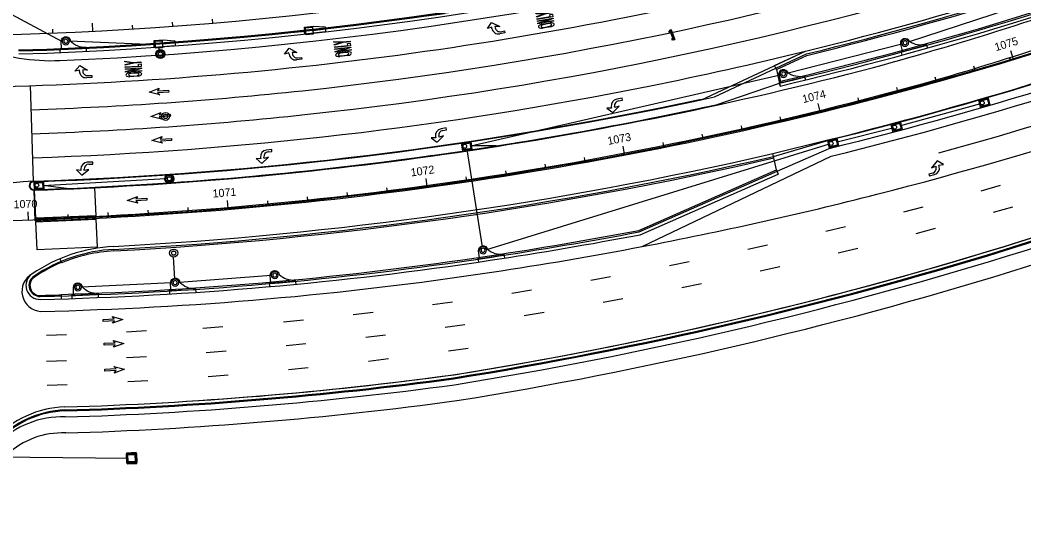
# Model space of a CAD drawing. Extents: x 468143 to 491361, y 1438528 to 1468730.
# Drawn here: x 489201 to 489702, y 1466536 to 1466783 of the extents above; entities that cross this region are included whole.
import ezdxf

# ---------------------------------------------------------------- set-up
doc = ezdxf.new("R2010")
doc.units = 0
doc.layers.add('Default', color=7, linetype='Continuous')
doc.layers.add('Xreference_dp', color=7, linetype='Continuous')

# ---------------------------------------------------------------- blocks, each defined once
blk = doc.blocks.new('POINT_DISPLAY')
at = {"layer": 'Default'}
blk.add_line((0, 0), (0, 0), dxfattribs=at)
blk = doc.blocks.new('InltCurb1_35')
at = {"layer": 'Default'}
for p, q in [((2.25, 2), (2.25, 5.5)), ((-10, 2), (-10, 0)), ((-10, 1.5), (3, 1.5)), ((3, 2), (2.25, 2)), ((3, 0), (3, 2))]:
    blk.add_line(p, q, dxfattribs=at)
for radius in [1.75, 1]:
    blk.add_circle((0, 5.5), radius, dxfattribs=at)
for centre, radius, start, end in [((-9.85, 12), 10, 269.1432, 319.4677), ((0, 5.5), 2.25, 0, 180)]:
    blk.add_arc(centre, radius, start, end, dxfattribs=at)
for p in [(-1.75, 5.5), (-1.75, 5.5), (-1.6, 6.2), (-1.22, 6.76), (-0.66, 7.12), (0, 7.75), (0, 7.25), (0, 7.25), (0, 5.5), (0, 5.5), (0.7, 7.1), (1.26, 6.72), (1.62, 6.16), (1.75, 5.5), (1.75, 5.5), (-1.62, 4.84), (-1.26, 4.28), (-0.7, 3.9), (0, 3.75), (0, 3.75), (0, 0), (0, 0), (0.66, 3.88), (1.22, 4.24), (1.6, 4.8)]:
    blk.add_blockref('POINT_DISPLAY', p, dxfattribs=at)
blk = doc.blocks.new('InltCurb7_40')
at = {"layer": 'Default'}
for p, q in [((2.5, 4), (-2.5, 4)), ((-2.5, 4), (-2.5, 0)), ((2.5, 3.25), (-2.5, 3.25)), ((-2.5, 0.75), (2.5, 0.75)), ((-2.5, 0), (2.5, 0)), ((2.5, 0), (2.5, 4))]:
    blk.add_line(p, q, dxfattribs=at)
blk.add_lwpolyline([(-2, 0.5), (2, 0.5), (2, 3.5), (-2, 3.5)], close=True, dxfattribs=at)
blk.add_circle((-1.04, 2.19), 1, dxfattribs=at)
for p in [(-2, 3.5), (-2, 2), (-2, 2), (-2, 0.5), (0, 4), (0, 3.5), (0, 3.5), (0, 2), (0, 2), (0, 0.5), (0, 0.5), (0, 0), (0, 0), (2, 3.5), (2, 2), (2, 2), (2, 0.5)]:
    blk.add_blockref('POINT_DISPLAY', p, dxfattribs=at)
blk = doc.blocks.new('MHCover2')
at = {"layer": 'Default'}
for radius in [2, 1.06, 1]:
    blk.add_circle((0, 0), radius, dxfattribs=at)
for p in [(-2, 0), (-2, 0), (-1.83, 0.81), (-1.39, 1.43), (-0.75, 1.85), (0, 2.5), (0, 2), (0, 2), (0, 0), (0, 0), (0, 0), (0.81, 1.83), (1.43, 1.39), (1.85, 0.75), (2, 0), (2, 0), (-1.85, -0.75), (-1.43, -1.39), (-0.81, -1.83), (0, -2), (0, -2), (0, -2.5), (0.75, -1.85), (1.39, -1.43), (1.83, -0.81)]:
    blk.add_blockref('POINT_DISPLAY', p, dxfattribs=at)
blk = doc.blocks.new('PBottom35Dia')
at = {"layer": 'Default'}
for radius in [2.25, 1.75, 1.75]:
    blk.add_circle((0, 0), radius, dxfattribs=at)
for p in [(-1.75, 0), (-1.75, 0), (-1.6, 0.7), (-1.22, 1.26), (-0.66, 1.62), (0, 1.75), (0, 1.75), (0, 1.75), (0, 0), (0, 0), (0.7, 1.6), (1.26, 1.22), (1.62, 0.66), (1.75, 0), (1.75, 0), (-1.62, -0.66), (-1.26, -1.22), (-0.7, -1.6), (0, -1.75), (0, -1.75), (0, -1.75), (0.66, -1.62), (1.22, -1.26), (1.6, -0.7)]:
    blk.add_blockref('POINT_DISPLAY', p, dxfattribs=at)
blk = doc.blocks.new('DBIDnoPvt')
at = {"layer": 'Default'}
for p, q in [((2.21, 2.71), (-2.21, 2.71)), ((-2.21, 2.71), (-2.21, -2.71)), ((-1.54, 2.23), (-1.54, -2.23)), ((1.54, 2.23), (-1.54, 2.23)), ((1.54, 2.04), (-1.54, 2.04)), ((1.54, -2.23), (1.54, 2.23)), ((2.21, -2.71), (2.21, 2.71)), ((-2.21, -2.71), (2.21, -2.71)), ((-1.54, -2.04), (1.54, -2.04)), ((-1.54, -2.23), (1.54, -2.23))]:
    blk.add_line(p, q, dxfattribs=at)
for p in [(-1.54, 2.04), (-1.54, 0), (-1.54, 0), (0, 2.71), (0, 2.04), (0, 2.04), (1.54, 2.04), (-1.54, -2.04), (0, 0), (0, 0), (0, -2.04), (0, -2.04), (0, -2.71), (1.54, 0), (1.54, 0), (1.54, -2.04)]:
    blk.add_blockref('POINT_DISPLAY', p, dxfattribs=at)
blk = doc.blocks.new('JBottom35x40')
at = {"layer": 'Default'}
for p, q in [((-2.42, 2.67), (-2.42, -2.67)), ((2.42, 2.67), (-2.42, 2.67)), ((-1.75, -2), (-1.75, 2)), ((-1.75, 2), (1.75, 2)), ((1.75, 2), (1.75, -2)), ((2.42, -2.67), (2.42, 2.67)), ((-2.42, -2.67), (2.42, -2.67)), ((1.75, -2), (-1.75, -2))]:
    blk.add_line(p, q, dxfattribs=at)
for p in [(-1.75, 2), (-1.75, 0), (-1.75, 0), (0, 2), (0, 2), (0, 2), (0, 0), (0, 0), (0, 0), (1.75, 2), (1.75, 0), (1.75, 0), (-1.75, -2), (0, -2), (0, -2), (0, -2), (1.75, -2)]:
    blk.add_blockref('POINT_DISPLAY', p, dxfattribs=at)
blk = doc.blocks.new('InltCurb5')
at = {"layer": 'Default'}
for p, q in [((-2.25, 3.5), (-8, 2.5)), ((-8, 2.5), (-8, 0)), ((-8, 1.5), (2.5, 1.5)), ((-8, 0), (2.5, 0)), ((2.25, 3.5), (-2.25, 3.5)), ((-1.96, 0), (-1.96, 1.5)), ((1.95, 0), (1.95, 1.5)), ((2.25, 2), (2.25, 3.5)), ((2.5, 2), (2.25, 2)), ((2.5, 0), (2.5, 2))]:
    blk.add_line(p, q, dxfattribs=at)
blk.add_lwpolyline([(-1.75, -0.5), (1.75, -0.5), (1.75, 3), (-1.75, 3)], close=True, dxfattribs=at)
for p in [(-1.75, 3), (-1.75, 1.25), (-1.75, 1.25), (0, 3.5), (0, 3), (0, 3), (0, 1.25), (0, 1.25), (1.75, 3), (1.75, 1.25), (1.75, 1.25), (-1.75, -0.5), (0, 0), (0, 0), (0, -0.5), (0, -0.5), (1.75, -0.5)]:
    blk.add_blockref('POINT_DISPLAY', p, dxfattribs=at)
blk = doc.blocks.new('SN')
at = {"layer": 'Default'}
for p, q in [((-0.064, 0.008), (-0.064, -0.008)), ((0.064, 0.008), (-0.064, 0.008)), ((0.064, -0.008), (0.064, 0.008)), ((-0.064, -0.008), (0.064, -0.008))]:
    blk.add_line(p, q, dxfattribs=at)
blk.add_lwpolyline([(-0.064, 0.008), (0.064, 0.008), (0.064, -0.008), (-0.064, -0.008)], close=True, dxfattribs=at)
for centre, start, end in [((-0.051, 0.02), 0, 180), ((-0.051, 0.02), 180, 0), ((0.05, 0.02), 0, 180), ((0.05, 0.02), 180, 0)]:
    blk.add_arc(centre, 0.00691, start, end, dxfattribs=at)
blk = doc.blocks.new('DAThru_1')
at = {"layer": 'Default'}
blk.add_lwpolyline([(4.58, -1.67), (5.58, -0.5), (0, -0.5), (0, 0.5), (5.58, 0.5), (4.58, 1.67), (9.83, 0), (4.58, -1.67)], dxfattribs=at)
blk = doc.blocks.new('DARightTurn')
at = {"layer": 'Default'}
for points in [[(2, 2.17), (0, 2.17), (0, 3.17), (2.67, 3.17)], [(5.67, -3.17), (2, -0.5), (4.33, -0.83), (4.33, -0.17)], [(6, -0.17), (6, -0.83), (8.25, -0.5), (5.67, -3.17)]]:
    blk.add_lwpolyline(points, dxfattribs=at)
for centre, radius in [((2, -0.17), 2.33), ((2.67, -0.17), 3.33)]:
    blk.add_arc(centre, radius, 360, 90, dxfattribs=at)
blk = doc.blocks.new('ONLY_5')
at = {"layer": 'Default'}
for p, q in [((1.94, 3.96), (6.06, 3.96)), ((6.06, 1.96), (1.94, 1.96)), ((5.6, 3.63), (2.4, 3.63)), ((2.4, 2.29), (5.6, 2.29))]:
    blk.add_line(p, q, dxfattribs=at)
for points in [[(0, -0.12), (0, 0.21), (5, 1.13), (0, 1.13), (0, 1.46), (8, 1.46), (8, 1.13), (2.9, 0.21), (8, 0.21), (8, -0.12), (0, -0.12)], [(1.33, -2.12), (0, -2.12), (0, -0.79), (8, -0.79), (8, -1.12), (1.33, -1.12), (1.33, -2.12)], [(8, -3.96), (3.67, -3.12), (0, -3.12), (0, -2.79), (3.67, -2.79), (8, -1.96), (8, -2.3), (4.57, -2.96), (8, -3.62), (8, -3.96)]]:
    blk.add_lwpolyline(points, dxfattribs=at)
for major_axis, ratio, start_param, end_param in [((4, 0), 0.291667, 2.111896, 4.171289), ((2.67, 0), 0.3125, 2.214297, 4.068888), ((2.67, 0), 0.3125, 5.35589, 7.210481), ((4, 0), 0.291667, 5.253489, 7.312882)]:
    blk.add_ellipse((4, 2.96), major_axis=major_axis, ratio=ratio, start_param=start_param, end_param=end_param, dxfattribs=at)
blk = doc.blocks.new('DALeftTurn_1')
at = {"layer": 'Default'}
for points in [[(5.67, 3.17), (2, 0.5), (4.33, 0.83), (4.33, 0.17)], [(6, 0.17), (6, 0.83), (8.25, 0.5), (5.67, 3.17)], [(2, -2.17), (0, -2.17), (0, -3.17), (2.67, -3.17)]]:
    blk.add_lwpolyline(points, dxfattribs=at)
for centre, radius in [((2, 0.17), 2.33), ((2.67, 0.17), 3.33)]:
    blk.add_arc(centre, radius, 270, 0, dxfattribs=at)
blk = doc.blocks.new('DAMerge_2')
at = {"layer": 'Default'}
blk.add_lwpolyline([(0.71, -4.09), (0, -3.39), (3.95, 0.56), (2.42, 0.68), (7.31, 3.21), (4.77, -1.68), (4.66, -0.15), (0.71, -4.09)], dxfattribs=at)
blk = doc.blocks.new('DAMerge_6')
at = {"layer": 'Default'}
blk.add_lwpolyline([(0.71, -4.09), (0, -3.39), (3.95, 0.56), (2.42, 0.68), (7.31, 3.21), (4.77, -1.68), (4.66, -0.15), (0.71, -4.09)], dxfattribs=at)

msp = doc.modelspace()

# ---------------------------------------------------------------- linework, layer by layer
at = {"layer": 'Xreference_dp'}
for p, q in [((489644.78, 1466771.71), (489819.77, 1466829.08)), ((489156.91, 1466806.54), (489221.99, 1466771.96)), ((489297.15, 1466781.07), (489296.99, 1466783.06)), ((489347.2, 1466777.31), (489413, 1466785.86)), ((489217.32, 1466776.08), (489217.24, 1466778.08)), ((489237.3, 1466777), (489237.09, 1466780.99)), ((489257.26, 1466778.13), (489257.14, 1466780.13)), ((489343.72, 1466776.93), (489271.99, 1466770.5)), ((489277.22, 1466779.49), (489277.07, 1466781.49)), ((489268.5, 1466770.27), (489225.49, 1466772.11)), ((489270.49, 1466767.34), (489270.36, 1466768.64)), ((489541.29, 1466742.82), (489593.25, 1466767.08)), ((489577.82, 1466759.88), (489593.25, 1466767.08)), ((489584.04, 1466756.12), (489641.4, 1466770.77)), ((489697.09, 1466763.37), (489695.93, 1466767.19)), ((489578.46, 1466758.52), (489593.75, 1466765.66)), ((489578.77, 1466757.84), (489594, 1466764.95)), ((489694.84, 1466763.7), (489696.53, 1466762.67)), ((489547.89, 1466744.25), (489578.46, 1466758.52)), ((489578.46, 1466758.52), (489577.82, 1466759.88)), ((489578.77, 1466757.84), (489578.46, 1466758.52)), ((489578.77, 1466757.84), (489580.36, 1466751.12)), ((489676.18, 1466757.92), (489677.58, 1466757.07)), ((489677.91, 1466757.68), (489677.36, 1466759.61)), ((489426.05, 1466719.81), (489580.64, 1466755.3)), ((489658.68, 1466752.2), (489658.14, 1466754.13)), ((489205.92, 1466749.84), (489207.5, 1466702.12)), ((489548.74, 1466740.34), (489580.37, 1466751.12)), ((489548.74, 1466740.34), (489567.63, 1466746.78)), ((489580.37, 1466751.12), (489580.71, 1466749.66)), ((489639.39, 1466746.93), (489638.87, 1466748.86)), ((489620.04, 1466741.85), (489619.55, 1466743.79)), ((489600.65, 1466736.98), (489599.69, 1466740.86)), ((489680.75, 1466740.78), (489640.84, 1466729.72)), ((489581.2, 1466732.31), (489580.74, 1466734.26)), ((489561.7, 1466727.84), (489561.27, 1466729.79)), ((489636.98, 1466728.69), (489609.07, 1466721.55)), ((489542.16, 1466723.58), (489541.75, 1466725.54)), ((489576.93, 1466715.92), (489603.83, 1466722.57)), ((489577.27, 1466714.46), (489603.89, 1466722.33)), ((489431.96, 1466669.39), (489424.29, 1466718.03)), ((489438.69, 1466719.73), (489426.05, 1466719.81)), ((489605.19, 1466720.59), (489433.95, 1466667.92)), ((489502.95, 1466715.67), (489502.2, 1466719.6)), ((489522.58, 1466719.53), (489522.18, 1466721.49)), ((489579.11, 1466707.09), (489605.18, 1466718.53)), ((489483.29, 1466712.03), (489482.93, 1466714)), ((489511.76, 1466669.51), (489606.13, 1466714.64)), ((489578.81, 1466707.77), (489576.93, 1466715.92)), ((489443.85, 1466705.36), (489443.54, 1466707.33)), ((489463.59, 1466708.59), (489463.25, 1466710.56)), ((489509.97, 1466677.56), (489578.81, 1466707.77)), ((489510.19, 1466676.84), (489579.11, 1466707.09)), ((489578.81, 1466707.77), (489579.71, 1466705.71)), ((489212.31, 1466700.03), (489273.76, 1466703.44)), ((489404.28, 1466699.51), (489403.74, 1466703.48)), ((489424.08, 1466702.33), (489423.79, 1466704.31)), ((489510.64, 1466675.4), (489579.71, 1466705.71)), ((489208.45, 1466682.39), (489207.89, 1466697.63)), ((489224.06, 1466698.48), (489212.31, 1466700.03)), ((489364.6, 1466694.5), (489364.37, 1466696.49)), ((489384.45, 1466696.9), (489384.2, 1466698.89)), ((489690.55, 1466699.92), (489680.94, 1466697.17)), ((489304.9, 1466688.54), (489304.56, 1466692.52)), ((489324.82, 1466690.32), (489324.63, 1466692.31)), ((489344.72, 1466692.3), (489344.51, 1466694.29)), ((489205.07, 1466682.78), (489204.95, 1466686.78)), ((489245.04, 1466684.46), (489244.93, 1466686.45)), ((489265, 1466685.61), (489264.88, 1466687.6)), ((489284.96, 1466686.97), (489284.81, 1466688.96)), ((489652.01, 1466689.23), (489642.34, 1466686.68)), ((489696.69, 1466689.2), (489687.07, 1466686.44)), ((489225.06, 1466683.51), (489224.98, 1466685.51)), ((489613.25, 1466679.32), (489603.53, 1466676.97)), ((489658.16, 1466678.45), (489648.49, 1466675.89)), ((489574.31, 1466670.2), (489564.54, 1466668.05)), ((489619.42, 1466668.48), (489609.71, 1466666.11)), ((489220.85, 1466663.42), (489221.72, 1466661.35)), ((489278.29, 1466653.2), (489277.6, 1466664.33)), ((489535.18, 1466661.88), (489525.38, 1466659.92)), ((489580.49, 1466659.29), (489570.73, 1466657.12)), ((489276.63, 1466651.37), (489231.55, 1466649.19)), ((489326.4, 1466655.07), (489280.62, 1466651.57)), ((489495.9, 1466654.35), (489486.06, 1466652.6)), ((489456.47, 1466647.62), (489446.59, 1466646.07)), ((489541.38, 1466650.89), (489531.58, 1466648.92)), ((489221.64, 1466643.35), (489221.55, 1466645.6)), ((489416.91, 1466641.7), (489407, 1466640.34)), ((489502.12, 1466643.29), (489492.27, 1466641.51)), ((489377.24, 1466636.58), (489367.31, 1466635.42)), ((489462.7, 1466636.47), (489452.83, 1466634.9)), ((489342.45, 1466632.74), (489332.5, 1466631.79)), ((489264.01, 1466627.36), (489254.02, 1466626.79)), ((489302.17, 1466629.37), (489292.2, 1466628.59)), ((489423.16, 1466630.46), (489413.25, 1466629.08)), ((489224.06, 1466625.36), (489214.06, 1466624.99)), ((489383.5, 1466625.24), (489373.57, 1466624.06)), ((489303.91, 1466617.22), (489293.94, 1466616.44)), ((489343.74, 1466620.83), (489333.79, 1466619.85)), ((489424.81, 1466618.57), (489414.91, 1466617.19)), ((489224.06, 1466612.41), (489214.06, 1466612.04)), ((489264.01, 1466614.41), (489254.02, 1466613.84)), ((489384.91, 1466613.33), (489374.98, 1466612.15)), ((489344.92, 1466608.89), (489334.97, 1466607.91)), ((489264.7, 1466602.43), (489254.71, 1466601.86)), ((489304.84, 1466605.25), (489294.87, 1466604.48)), ((489224.51, 1466600.42), (489214.51, 1466600.05)), ((488998.14, 1466566.74), (489254.9, 1466563.72))]:
    msp.add_line(p, q, dxfattribs=at)
for points in [[(489238.14, 1466698.76), (489238.69, 1466684.77), (489208.72, 1466683.59), (489208.17, 1466697.58)], [(489238.79, 1466683.24), (489239.41, 1466669.25), (489209.44, 1466667.92), (489208.82, 1466681.91)]]:
    msp.add_lwpolyline(points, close=True, dxfattribs=at)
for centre, radius, start, end in [((489145.02, 1468591.69), 1909.86, 245.36712, 306.9274), ((489143.9, 1468591.41), 1816.82, 245.36787, 299.96455), ((489145.02, 1468591.69), 1830.86, 272.37289, 300.83686), ((489145.02, 1468591.69), 1824.86, 271.73266, 299.99002), ((489145.02, 1468591.69), 1825.36, 271.73266, 299.99002), ((489145.02, 1468591.69), 1826.86, 271.73266, 299.99002), ((489145.02, 1468591.69), 1854.86, 276.09654, 299.92655), ((489145.02, 1468591.69), 1866.86, 276.09086, 299.92655), ((489145.02, 1468591.69), 1878.86, 283.80177, 298.53195), ((489145.02, 1468591.69), 1878.86, 283.80177, 298.53195), ((489145.02, 1468591.69), 1880.36, 283.80626, 298.53195), ((489145.02, 1468591.69), 1881.11, 283.80851, 298.53195), ((489145.02, 1468591.69), 1910.36, 283.79147, 298.7751), ((489145.02, 1468591.69), 1890.61, 283.30727, 297.57606), ((489145.02, 1468591.69), 1891.36, 283.30727, 297.57606), ((489145.02, 1468591.69), 1892.86, 283.30727, 297.57606), ((489145.02, 1468591.69), 1924.61, 283.79147, 299.33378), ((489145.02, 1468591.69), 1924.86, 283.79147, 298.80179), ((489145.02, 1468591.69), 1928.86, 283.80177, 298.80179), ((489145.02, 1468591.69), 1932.86, 283.80177, 298.79546), ((489145.02, 1468591.69), 1956.86, 284.31651, 299.76158), ((489145.02, 1468591.69), 1944.86, 285.35186, 299.36432), ((489145.02, 1468591.69), 1842.86, 270.16616, 283.80836), ((489217.57, 1468271.43), 1566.97, 285.15473, 290.52137), ((489217.57, 1468271.43), 1581.47, 286.19088, 290.51522), ((489216.69, 1466862.32), 100, 248.9768, 272.3729), ((489097.74, 1468600.78), 2020.78, 279.09522, 295.12185), ((489097.74, 1468600.78), 2022.28, 279.09522, 295.12185), ((489097.74, 1468600.78), 2022.78, 279.09522, 295.12185), ((489097.69, 1468600.77), 2020.79, 279.11452, 295.12334), ((489145.02, 1468591.69), 1878.86, 281.36009, 283.80177), ((489097.74, 1468600.78), 2025.78, 279.09355, 295.12185), ((489145.02, 1468591.69), 1895.11, 271.90106, 284.74051), ((489097.74, 1468600.78), 2033.78, 279.09089, 295.12185), ((489145.02, 1468591.69), 1909.36, 271.90255, 285.60177), ((489145.02, 1468591.69), 1910.36, 271.90265, 285.60177), ((489145.02, 1468591.69), 1854.86, 271.89355, 276.09831), ((489145.02, 1468591.69), 1878.86, 271.89355, 281.36009), ((489145.02, 1468591.69), 1890.61, 271.89355, 282.09704), ((489145.02, 1468591.69), 1890.86, 271.90106, 282.30177), ((489145.02, 1468591.69), 1894.86, 271.90106, 282.30177), ((489145.02, 1468591.69), 1894.86, 278.91566, 282.30177), ((489145.02, 1468591.69), 1866.86, 271.89355, 276.09134), ((489145.02, 1468591.69), 1894.86, 272.39065, 277.95176), ((489145.02, 1468591.69), 1924.86, 273.05523, 282.96676), ((489145.02, 1468591.69), 1924.86, 273.05523, 282.96676), ((489145.02, 1468591.69), 1926.36, 273.05523, 282.96676), ((489145.02, 1468591.69), 1927.11, 273.05523, 282.96676), ((489210.81, 1466601.92), 100.25, 91.8935, 183.3796), ((489207.72, 1466699.87), 2.25, 95.6574, 274.4755), ((489207.82, 1466699.88), 2, 91.9011, 271.9011), ((489145.02, 1468591.69), 1956.86, 280.80177, 284.31651), ((489145.02, 1468591.69), 1948.61, 278.5701, 280.79446), ((489145.02, 1468591.69), 1949.36, 278.5701, 280.79679), ((489145.02, 1468591.69), 1950.86, 278.5701, 280.80177), ((489251.88, 1466589.68), 80, 93.0552, 124.2035), ((489251.88, 1466589.68), 80, 93.0552, 124.2035), ((489251.88, 1466589.68), 78.5, 93.0552, 124.2035), ((489251.88, 1466589.68), 77.75, 93.0552, 112.8261), ((489145.02, 1468591.69), 1956.86, 278.5701, 280.80177), ((489251.88, 1466589.68), 78, 112.8261, 124.2035), ((489167.8, 1468440.54), 1796.5, 271.37707, 278.5701), ((489167.8, 1468440.54), 1798, 271.37707, 278.5701), ((489167.8, 1468440.54), 1795.75, 271.71501, 278.5701), ((489167.8, 1468440.54), 1804, 271.37707, 278.5701), ((489211.92, 1466647.11), 10.08, 119.8395, 265.6409), ((489210.84, 1466650.06), 7, 124.2035, 271.3771), ((489210.84, 1466650.06), 5.5, 124.2035, 271.3771), ((489210.84, 1466650.06), 5.5, 124.2035, 271.3771), ((489210.84, 1466650.06), 5, 124.2035, 271.3771), ((489210.84, 1466650.06), 5, 124.2035, 271.3771), ((489167.8, 1468440.54), 1796, 271.37707, 271.71508), ((489167.8, 1468440.54), 1852, 271.71717, 277.75777), ((489167.8, 1468440.54), 1852, 271.71717, 277.73835), ((489167.8, 1468440.54), 1853.5, 271.71717, 277.73835), ((489167.8, 1468440.54), 1854, 271.71717, 277.73835), ((489167.8, 1468440.54), 1857, 271.71717, 277.74018), ((489167.8, 1468440.54), 1865, 271.71717, 277.74308), ((489224.8, 1466539.4), 50, 91.7172, 183.3573), ((489224.8, 1466539.4), 50, 91.7172, 183.3796), ((489224.8, 1466539.4), 48.5, 91.7172, 183.3573), ((489224.8, 1466539.4), 48, 91.7172, 183.3573), ((489221.79, 1466539.41), 45, 87.8888, 183.6184), ((489221.87, 1466536.42), 40, 87.3937, 179.3692)]:
    msp.add_arc(centre, radius, start, end, dxfattribs=at)

# ---------------------------------------------------------------- block references
for name, p, rotation in [('ONLY_5', (489467.23, 1466783.51), -169.80377010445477), ('DARightTurn', (489442.59, 1466779.28), -169.80377010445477), ('ONLY_5', (489366.13, 1466769.03), -172.92257476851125), ('MHCover2', (489271.05, 1466765.68), 86.55174435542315), ('PBottom35Dia', (489271.05, 1466765.68), 86.55174435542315), ('DARightTurn', (489341.29, 1466766.14), -172.92257476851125), ('ONLY_5', (489261.52, 1466758.6), -176.22391568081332), ('DARightTurn', (489236.56, 1466757.15), -176.22391568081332), ('DAMerge_2', (489272.94, 1466744.1), 138.68263115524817), ('DAMerge_6', (489272.94, 1466744.1), 138.68263115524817), ('DALeftTurn_1', (489502.16, 1466740.43), -170.88566221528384), ('InltCurb7_40', (489683.22, 1466739.41), 16.08893287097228), ('DAMerge_2', (489273.76, 1466732.09), 138.68263115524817), ('DAMerge_6', (489273.76, 1466732.09), 138.68263115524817), ('MHCover2', (489273.62, 1466734.48), 86.55174435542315), ('InltCurb7_40', (489639.43, 1466727.27), 14.964635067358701), ('DAMerge_2', (489274.33, 1466719.97), 138.68263115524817), ('DAMerge_6', (489274.33, 1466719.97), 138.68263115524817), ('DALeftTurn_1', (489414.37, 1466725.61), -170.82156880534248), ('InltCurb7_40', (489424.36, 1466717.54), 8.40176266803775), ('InltCurb7_40', (489607.61, 1466719.13), 13.876033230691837), ('DALeftTurn_1', (489327, 1466714.81), -173.69758439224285), ('DALeftTurn_1', (489237.27, 1466708.5), -178.2870050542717), ('DALeftTurn_1', (489654.4, 1466707.79), 14.934743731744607), ('InltCurb7_40', (489210.38, 1466697.96), 1.976767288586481), ('MHCover2', (489275.51, 1466703.34), 86.55174435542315), ('PBottom35Dia', (489275.51, 1466703.34), 86.55174435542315), ('DAThru_1', (489264.27, 1466693.15), -176.52144757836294), ('MHCover2', (489277.64, 1466666.23), 86.55174435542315), ('DAMerge_2', (489244.67, 1466635.61), -42.401456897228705), ('DAMerge_6', (489244.67, 1466635.61), -42.401456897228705), ('DAMerge_2', (489245.12, 1466623.69), -42.401456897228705), ('DAMerge_6', (489245.12, 1466623.69), -42.401456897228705), ('DAMerge_2', (489245.56, 1466610.78), -42.401456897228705), ('DAMerge_6', (489245.56, 1466610.78), -42.401456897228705), ('DBIDnoPvt', (489256.65, 1466563.78), 92.27334926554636), ('JBottom35x40', (489256.65, 1466563.78), 2.273349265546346)]:
    msp.add_blockref(name, p, dxfattribs=dict(at, rotation=rotation))
for name, p, yscale, rotation in [('InltCurb5', (489345.59, 1466775.88), -0.9999999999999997, -173.73207789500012), ('InltCurb1_35', (489223.97, 1466766.54), -0.999999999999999, -177.57031937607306), ('InltCurb5', (489270.33, 1466769.14), -1, -176.1061790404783), ('InltCurb1_35', (489644.56, 1466765.94), -1, -164.54695138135), ('InltCurb1_35', (489583.63, 1466750.36), -1, -166.49524070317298), ('InltCurb1_35', (489433.04, 1466662.22), -1, -171.45524695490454), ('InltCurb1_35', (489328.65, 1466649.75), -1.0000000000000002, -174.70775783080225), ('InltCurb1_35', (489230, 1466643.63), -0.9999999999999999, -177.90591065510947), ('InltCurb1_35', (489278.65, 1466645.96), -1, -177.1933497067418)]:
    msp.add_blockref(name, p, dxfattribs=dict(at, yscale=yscale, rotation=rotation))
at = {"layer": 'Xreference_dp', "xscale": 40.0000000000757, "yscale": 40.00000000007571, "rotation": 110.63901817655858}
msp.add_blockref('SN', (489526.75, 1466775.25), dxfattribs=at)

# ---------------------------------------------------------------- texts
at = {"layer": 'Xreference_dp'}
for s, rotation, p in [('1075', 16.8018, (489688.48, 1466767.03)), ('1074', 13.8018, (489592.24, 1466741.09)), ('1073', 10.8018, (489494.77, 1466720.22)), ('1072', 7.8018, (489396.35, 1466704.48)), ('1071', 4.8018, (489297.24, 1466693.92)), ('1070', 1.8018, (489197.71, 1466688.55))]:
    msp.add_text(s, height=4, rotation=rotation, dxfattribs=at).set_placement(p)

doc.saveas('drawing.dxf')
